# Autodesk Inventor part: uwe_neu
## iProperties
Shininess: 20.0
Length Units: 11269
Angle Units: 11279
Time Units: 11290
Mass Units: 11283
Length Display Precision: 3
Angle Display Precision: 2
Created: 2003-05
Part Number: uwe_neu
Material: Standard
Description: Artikel
Document SubType Name: Modellieren
Designer: Seiler U.
Cost Center: 0,061 kg
Authority: 60859,8 mm^3
Density: 0.0
Volumn: 0.0
Area: 0.0
PropertySet Name: Model Information
Control State: 0
Master: False
Checked Out: False
SaveDate: 2003-05-13
SaveTime: 20:45
TotalMass: 0,061 kg
TotalVolume: 60859,8 mm^3
Title: Werkstoff
Subject: Werkstoff-Nr.
Author: Seiler U.
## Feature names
1. Extrusion1
2. Extrusion4
3. Extrusion5
4. Extrusion2
5. Höhe eingegeben Extrusion3 [Extrusion]
